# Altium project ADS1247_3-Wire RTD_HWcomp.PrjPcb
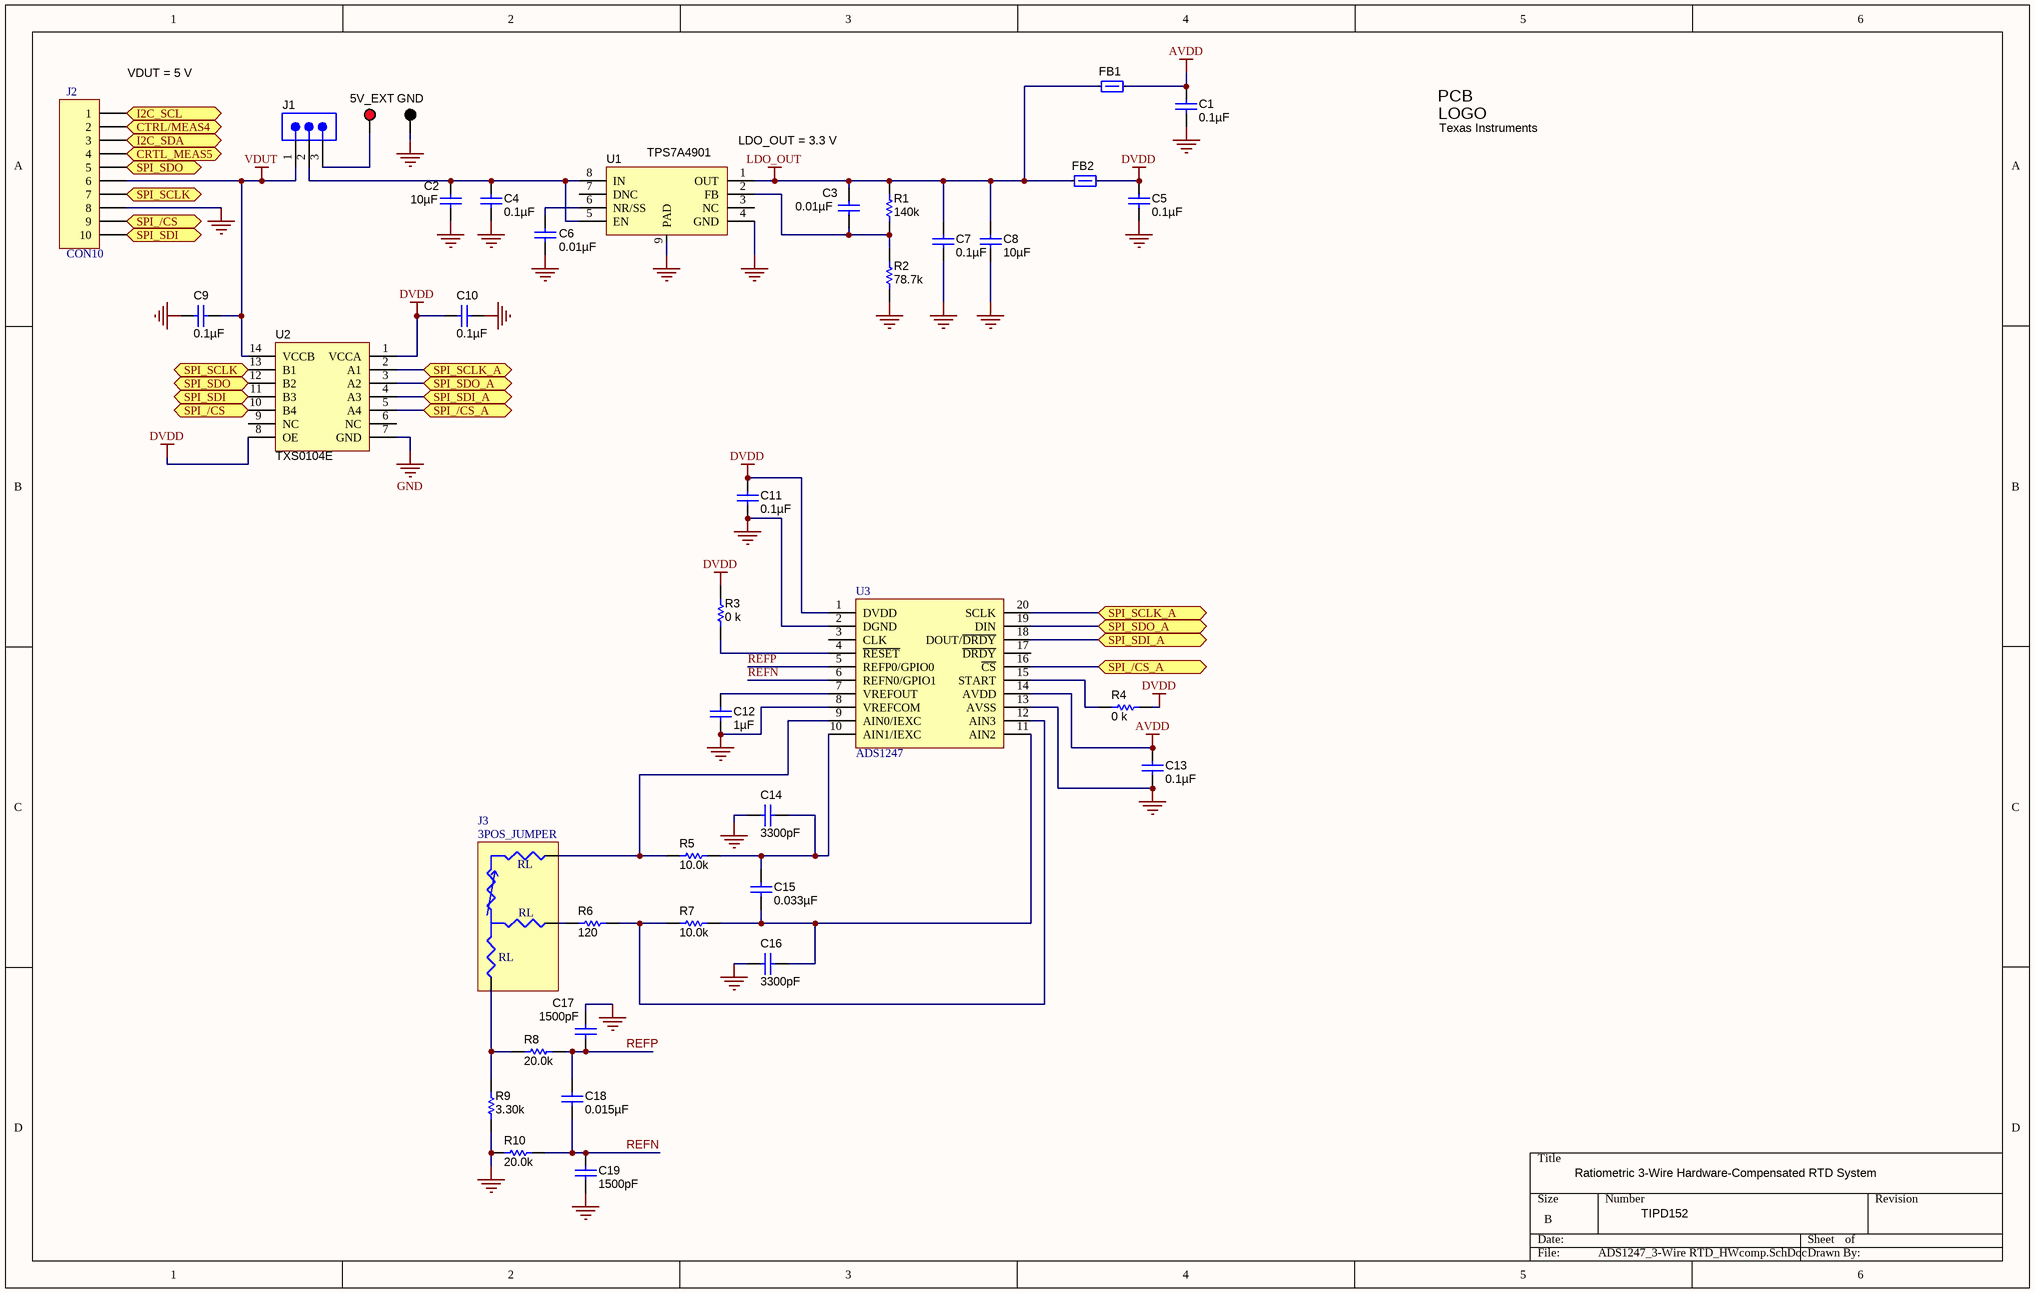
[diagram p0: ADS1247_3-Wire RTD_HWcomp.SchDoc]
TechSupport: http://www.ti.com/support; SCH_Rev: X1; PRJ_Title: Change me in menu Project|Project Options|Parameters; PRJ_Customer: Public Release; PRJ_BasePN: xxxxxx; PCB_SilkRev: REV A; PCB_CopperRev: 001; CopyrightYear: 2012
1 sheet, 40 parts. Net scope: flat (ports and power ports of the same name join across sheets).
Board file: ADS1247_3-Wire RTD_HWcomp.PcbDoc

## Sheet ADS1247_3-Wire RTD_HWcomp.SchDoc
size B; SheetNumber: 0; SheetTotal: 0

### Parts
C1  ValueDisplayed: 0.1µF  [0603]  (hidden comment: GRM188R71H104KA93D)
C2  ValueDisplayed: 10µF  [1210]  (hidden comment: C3225X7R1E106M)
C3  ValueDisplayed: 0.01µF  [0603]  (hidden comment: C0603C103J5RACTU)
C4  ValueDisplayed: 0.1µF  [0603]  (hidden comment: GRM188R71H104KA93D)
C5  ValueDisplayed: 0.1µF  [0603]  (hidden comment: GRM188R71H104KA93D)
C6  ValueDisplayed: 0.01µF  [0603]  (hidden comment: C0603C103J5RACTU)
C7  ValueDisplayed: 0.1µF  [0603]  (hidden comment: GRM188R71H104KA93D)
C8  ValueDisplayed: 10µF  [1210]  (hidden comment: C3225X7R1E106M)
C9  ValueDisplayed: 0.1µF  [0603]  (hidden comment: GRM188R71H104KA93D)
C10  ValueDisplayed: 0.1µF  [0603]  (hidden comment: GRM188R71H104KA93D)
C11  ValueDisplayed: 0.1µF  [0603]  (hidden comment: GRM188R71H104KA93D)
C12  ValueDisplayed: 1µF  [0603]  (hidden comment: C1608X7R1C105K)
C13  ValueDisplayed: 0.1µF  [0603]  (hidden comment: GRM188R71H104KA93D)
C14  ValueDisplayed: 3300pF  [0603]  (hidden comment: CL10C332JA8NNNC)
C15  ValueDisplayed: 0.033µF  [0805]  (hidden comment: C2012C0G1E333J125AA)
C16  ValueDisplayed: 3300pF  [0603]  (hidden comment: CL10C332JA8NNNC)
C17  ValueDisplayed: 1500pF  [0603]  (hidden comment: GRM1885C1E152JA01D)
C18  ValueDisplayed: 0.015µF  [0603]  (hidden comment: C0603C153J3GACTU)
C19  ValueDisplayed: 1500pF  [0603]  (hidden comment: GRM1885C1E152JA01D)
FB1  BLM18HG601SN1D  [0603]  (value not drawn)
FB2  BLM18HG601SN1D  [0603]  (value not drawn)
J1  TSW-103-07-G-S  [TSW-103-07-G-S]  (value not drawn)
J2  CON10  [DIP - 0.5 - 10]
J3  3POS_JUMPER  [3TERM_SCREW_CON_3.5MM]
Logo?  Texas Instruments  [TI_Stacked_Overlay_Small]  (no BOM)
R1  value 140k  [0603]  (hidden comment: ERA-3AEB1653V)
R2  value 78.7k  [0603]  (hidden comment: RG1608P-5112-B-T5)
R3  value 0 k  [0603]  (hidden comment: CRCW06031K00JNEA)
R4  value 0 k  [0603]  (hidden comment: CRCW06031K00JNEA)
R5  value 10.0k  [0603]  (hidden comment: RC0603FR-0710KL)
R6  value 120  [0603]  (hidden comment: RG1608P-121-B-T5)
R7  value 10.0k  [0603]  (hidden comment: RC0603FR-0710KL)
R8  value 20.0k  [0603]  (hidden comment: RC0603FR-0720KL)
R9  value 3.30k  [0805]  (hidden comment: RG2012L-332-L-T05)
R10  value 20.0k  [0603]  (hidden comment: RC0603FR-0720KL)
TP1  5V_EXT  [Keystone5005]
TP2  GND  [Keystone5006]
U1  TPS7A4901  [MUY08A_N]
U2  TXS0104E  [MTC14_N]
U3  ADS1247  [20-TSSOP(PW)]

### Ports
CRTL_MEAS5, CTRL/MEAS4, I2C_SCL, I2C_SDA, SPI_/CS, SPI_/CS_A, SPI_SCLK, SPI_SCLK_A, SPI_SDI, SPI_SDI_A, SPI_SDO, SPI_SDO_A

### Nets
AVDD: C1.1 C13.2 FB1.2 U3.14(AVDD)
DVDD: C5.1 C10.1 C11.2 FB2.2 R3.2 R4.2 U2.1(VCCA) U2.8(OE) U3.1(DVDD)
GND: C1.2 C2.2 C4.2 C5.2 C6.2 C7.2 C8.2 C9.2 C10.2 C11.1 C12.1 C13.1 C14.1 C16.1 C17.1 C19.1 J2.8 R2.1 R9.1 R10.2 TP2.1 U1.4(GND) U1.9(PAD) U2.7(GND) U3.2(DGND) U3.8(VREFCOM) U3.13(AVSS)
LDO_OUT: C3.1 C7.1 C8.1 FB1.1 FB2.1 R1.1 U1.1(OUT)
VDUT: C9.1 J1.1 J2.6 U2.14(VCCB)
REFN: C18.2 C19.2 R10.1 U3.6(REFN0/GPIO1)
REFP: C17.2 C18.1 R8.1 U3.5(REFP0/GPIO0)
NetC2_1: C2.1 C4.1 J1.2 U1.5(EN) U1.8(IN)
NetC3_2: C3.2 R1.2 R2.2 U1.2(FB)
NetC6_1: C6.1 U1.6(NR/SS)
NetC12_2: C12.2 U3.7(VREFOUT)
NetC14_2: C14.2 C15.2 R5.2 U3.10(AIN1/IEXC)
NetC15_1: C15.1 C16.2 R7.2 U3.11(AIN2)
NetJ1_3: J1.3 TP1.1
NetJ2_1: J2.1 ; port I2C_SCL
NetJ2_2: J2.2 ; port CTRL/MEAS4
NetJ2_3: J2.3 ; port I2C_SDA
NetJ2_4: J2.4 ; port CRTL_MEAS5
NetJ2_5: J2.5 U2.12(B2) ; port SPI_SDO
NetJ2_7: J2.7 U2.13(B1) ; port SPI_SCLK
NetJ2_9: J2.9 U2.10(B4) ; port SPI_/CS
NetJ2_10: J2.10 U2.11(B3) ; port SPI_SDI
NetJ3_1: J3.1(BLACK) R6.1
NetJ3_2: J3.2(RED) R5.1 U3.9(AIN0/IEXC)
NetJ3_3: J3.3(BLACK) R8.2 R9.2
NetR3_1: R3.1 U3.4(~{RESET})
NetR4_1: R4.1 U3.15(START)
NetR6_2: R6.2 R7.1 U3.12(AIN3)
NetU2_2: U2.2(A1) U3.20(SCLK) ; port SPI_SCLK_A
NetU2_3: U2.3(A2) U3.19(DIN) ; port SPI_SDO_A
NetU2_4: U2.4(A3) U3.18(DOUT/~{DRDY}) ; port SPI_SDI_A
NetU2_5: U2.5(A4) U3.16(~{CS}) ; port SPI_/CS_A

Not connected (* = marked no-connect by the designer): U1 3(NC) 7(DNC); U2 6(NC) 9(NC); U3 3(CLK) 17(~{DRDY})

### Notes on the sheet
- (near J2) VDUT = 5 V
- LDO_OUT = 3.3 V
- Ratiometric 3-Wire Hardware-Compensated RTD System
- TIPD152

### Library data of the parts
C1 C4 C5 C7 C9-C11 C13 = GRM188R71H104KA93D: CAP, CERM, 0.1uF, 50V, +/-10%, X7R, 0603; Manufacturer: MuRata; Polarized: N; CompType: Capacitor; U/M: EA; Cap_F: 0.0000001; Tolerance_%: 10; VDC_V: 50; TaMin_C: -55; TaMax_C: 125
C2 C8 = C3225X7R1E106M: CAP, CERM, 10uF, 25V, +/-20%, X7R, 1210; Manufacturer: TDK; Polarized: N; CompType: Capacitor; U/M: EA; Cap_F: 0.00001; Tolerance_%: 20; ESR_Ohm: 0.0027; Value1: 0.0027 ohm; VDC_V: 25; IRMS_A: 3; TaMin_C: -55; TaMax_C: 125
C3 C6 = C0603C103J5RACTU: CAP, CERM, 0.01uF, 50V, +/-5%, X7R, 0603; Manufacturer: Kemet; Polarized: N; CompType: Capacitor; U/M: EA; Cap_F: 0.00000001; Tolerance_%: 5; VDC_V: 50; TaMin_C: -55; TaMax_C: 125
C12 = C1608X7R1C105K: CAP, CERM, 1uF, 16V, +/-10%, X7R, 0603; Manufacturer: TDK; Polarized: N; CompType: Capacitor; U/M: EA; Cap_F: 0.000001; Tolerance_%: 10; ESR_Ohm: 0.0057; Value1: 0.0057 ohm; VDC_V: 16; TaMin_C: -55; TaMax_C: 125
C14 C16 = C1608C0G1H332J: 'CAP CER 3300PF 25V 5% NP0 0603; Manufacturer: Samsung Electro-Mech; Polarized: N; CompType: Capacitor; U/M: EA; Cap_F: 0.0000000033; Tolerance_%: 5; Value1: 0.0309 ohm; VDC_V: 50; Value2: 50V; TempCo: C0G/NP0; TaMin_C: -55; TaMax_C: 125
C15 = C2012C0G1E333J: CAP CER 0.033UF 25V 5% NP0 0805; Manufacturer: TDK; Polarized: N; CompType: Capacitor; U/M: EA; Cap_F: 0.000000033; Tolerance_%: 5; VDC_V: 25; TempCo: C0G/NP0; TaMin_C: -55; TaMax_C: 125
C17 C19 = C1608C0G1H152J: CAP CER 1500PF 25V 5% NP0 0603; Manufacturer: MuRata; Polarized: N; CompType: Capacitor; U/M: EA; Cap_F: 0.0000000015; Tolerance_%: 5; Value1: 0.039 ohm; VDC_V: 50; Value2: 50V; TempCo: C0G/NP0; TaMin_C: -55; TaMax_C: 125
C18 = GRM188R71E153KA01D: CAP CER 0.015UF 25V 5% NP0 0603; Manufacturer: Kemet; Polarized: N; CompType: Capacitor; U/M: EA; Cap_F: 0.000000015; Tolerance_%: 10; VDC_V: 25; TaMin_C: -55; TaMax_C: 125
FB1 FB2 = Ferrite_Bead: FERRITE CHIP 600 OHM 200MA 0603; Manufacturer: MuRata; U/M: EA
J1 = TSW-103-07-G-S: Header, TH, 100mil, 3x1, Gold plated, 230 mil above insulator; Manufacturer: Samtec, Inc.; SymbolCreator: a0799628; U/M: EA
J2 = CON10: Connector
J3 = RTD-3-WIRE
Logo? = TI_Logo: Texas Instrument Corporate Signature; SymbolCreator: codlsc
R1 = RT0603BRD07164KL: RES 165K OHM 1/10W .1% 0603 SMD; Manufacturer: Panasonic Electronic Components; CompType: Resistor; Res_ohm: 165000; Tolerance_%: 0.1; Value1: 0.1%; Value2: 0.1W; VDC_V: 75; TempCo: 25 ppm/C; EIA_Code: E192; U/M: EA
R2 = RG1608P-5112-B-T5: RES, 51.1k ohm, 0.1%, 0.1W, 0603; Manufacturer: Susumu Co Ltd; CompType: Resistor; Res_ohm: 51100; Value_Code: 51k1; Tolerance_%: 0.1; VDC_V: 75; TempCo: 25 ppm/C; EIA_Code: E192; U/M: EA
R3 R4 = CRCW06031K00JNEA: RES, 1.0k ohm, 5%, 0.1W, 0603; Manufacturer: Vishay-Dale; CompType: Resistor; Res_ohm: 1000; Value_Code: 1k00; Tolerance_%: 5; Power_W: 0.1; VDC_V: 75; TempCo: 200 ppm/C; EIA_Code: E24; U/M: EA
R5 R7 = RC0603FR-0710KL: RES, 10.0k ohm, 1%, 0.1W, 0603; Manufacturer: Yageo America; CompType: Resistor; Res_ohm: 10000; Value_Code: 10k0; Tolerance_%: 1; Power_W: 0.1; VDC_V: 150; TempCo: 200 ppm/C; EIA_Code: E96; U/M: EA
R6 = RG1608P-121-B-T5: RES, 120 ohm, 0.1%, 0.1W, 0603; Manufacturer: Susumu Co Ltd; CompType: Resistor; Value_Code: 120R; Tolerance_%: 0.1; VDC_V: 75; TempCo: 25 ppm/C; EIA_Code: E192; U/M: EA
R8 R10 = RC0603FR-0720KL: RES, 20.0k ohm, 1%, 0.1W, 0603; Manufacturer: Yageo America; CompType: Resistor; Res_ohm: 20000; Value_Code: 20k0; Tolerance_%: 1; Power_W: 0.1; VDC_V: 150; TempCo: 200 ppm/C; EIA_Code: E96; U/M: EA
R9 = RG2012P-822-B-T5: RES 3.3K OHM 0.1W 0.01% 0805; Manufacturer: Susumu Co Ltd; CompType: Resistor; Res_ohm: 8200; Value_Code: 3k30; Tolerance_%: 0.01; Power_W: 0.125; Value2: 0.125W; VDC_V: 100; U/M: EA
TP1 = 5005: Test Point, TH, Compact, Red; Manufacturer: Keystone; CompType: Test Point Loop; U/M: EA
TP2 = 5006: Test Point, TH, Compact, Black; Manufacturer: Keystone; CompType: Test Point Loop; U/M: EA
U1 = TPS7A4901: IC REG LDO ADJ .15A 8MSOP; Manufacturer: Texas Instruments Inc; PartNumber: TPS7A4901DGNR; SymbolVersion: use current date i.e. 2008-05-20; SymbolCreator: Use LDAP id; CompType: TPS; U/M: EA, IN, or GM
U2 = TXS0104E: Manufacturer: Used in BOM report; SymbolVersion: use current date i.e. 2008-05-20; SymbolCreator: Use LDAP id; CompType: Used in some BOM reports.  Useful for finding later.; U/M: EA, IN, or GM

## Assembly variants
-100A: all parts fitted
